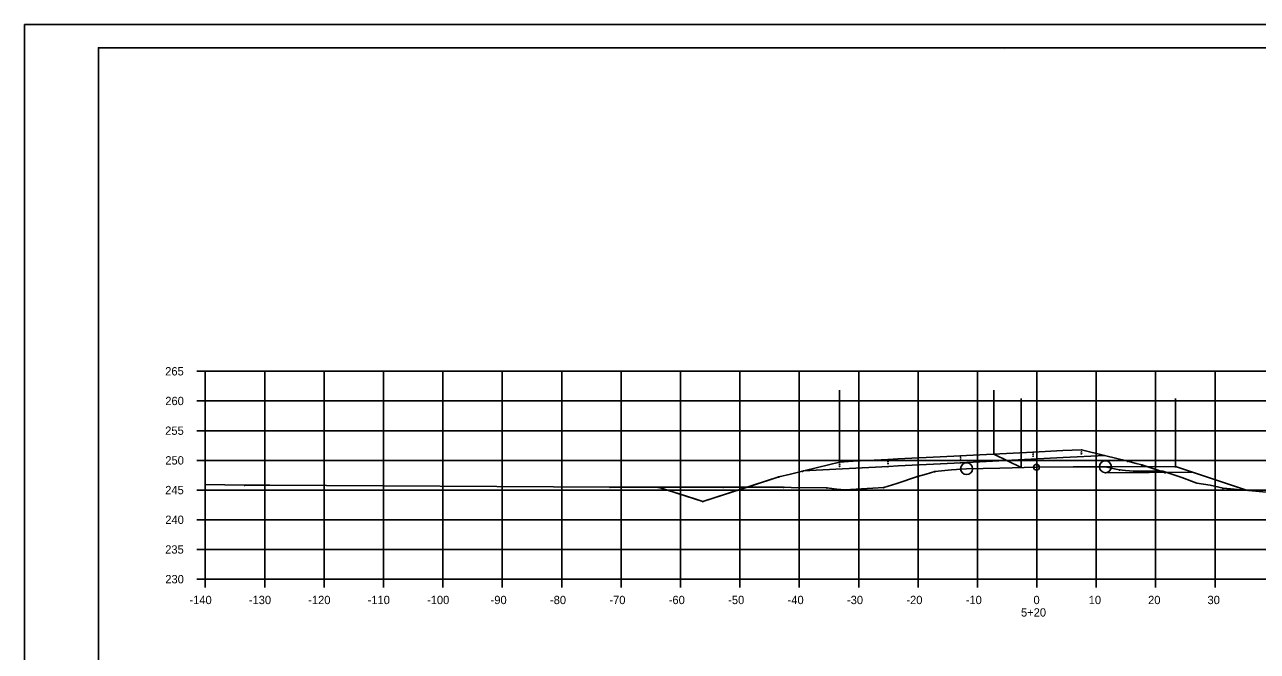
# Model space of a CAD drawing. Extents: x 1300404 to 1323571, y 234004 to 252077.
# Drawn here: x 1315546.9 to 1315754.4, y 241809.6 to 241915.1 of the extents above; entities that cross this region are included whole.
import ezdxf

# ---------------------------------------------------------------- set-up
doc = ezdxf.new("R2010")
doc.units = 0
for name, color, linetype in [('Default', 7, 'Continuous'), ('R_Axis', 7, 'Continuous'), ('R_Axis Annot', 7, 'Continuous'), ('R_Border', 7, 'Continuous'), ('R_Draft', 7, 'Continuous'), ('R_Exist Surface', 7, 'Continuous'), ('R_Fin Surface', 7, 'Continuous'), ('R_Grid', 7, 'Continuous'), ('R_MOT', 7, 'Continuous'), ('R_No Plot', 7, 'Continuous')]:
    doc.layers.add(name, color=color, linetype=linetype)

msp = doc.modelspace()

# ---------------------------------------------------------------- linework, layer by layer
at = {"layer": 'Default'}
for p, q in [((1315559.28, 241911.23), (1315875.46, 241911.23)), ((1315559.28, 241705.77), (1315559.28, 241911.23))]:
    msp.add_line(p, q, dxfattribs=at)
at = {"layer": 'R_Axis'}
for p, q in [((1315575.88, 241856.77), (1315577.28, 241856.77)), ((1315577.28, 241821.77), (1315577.28, 241856.77)), ((1315575.88, 241851.77), (1315577.28, 241851.77)), ((1315575.88, 241846.77), (1315577.28, 241846.77)), ((1315575.88, 241841.77), (1315577.28, 241841.77)), ((1315575.88, 241836.77), (1315577.28, 241836.77)), ((1315575.88, 241831.77), (1315577.28, 241831.77)), ((1315575.88, 241826.77), (1315577.28, 241826.77)), ((1315575.88, 241821.77), (1315577.28, 241821.77)), ((1315577.28, 241821.77), (1315857.28, 241821.77)), ((1315577.28, 241820.37), (1315577.28, 241821.77)), ((1315587.28, 241820.37), (1315587.28, 241821.77)), ((1315597.28, 241820.37), (1315597.28, 241821.77)), ((1315607.28, 241820.37), (1315607.28, 241821.77)), ((1315617.28, 241820.37), (1315617.28, 241821.77)), ((1315627.28, 241820.37), (1315627.28, 241821.77)), ((1315637.28, 241820.37), (1315637.28, 241821.77)), ((1315647.28, 241820.37), (1315647.28, 241821.77)), ((1315657.28, 241820.37), (1315657.28, 241821.77)), ((1315667.28, 241820.37), (1315667.28, 241821.77)), ((1315677.28, 241820.37), (1315677.28, 241821.77)), ((1315687.28, 241820.37), (1315687.28, 241821.77)), ((1315697.28, 241820.37), (1315697.28, 241821.77)), ((1315707.28, 241820.37), (1315707.28, 241821.77)), ((1315717.28, 241820.37), (1315717.28, 241821.77)), ((1315727.28, 241820.37), (1315727.28, 241821.77)), ((1315737.28, 241820.37), (1315737.28, 241821.77)), ((1315747.28, 241820.37), (1315747.28, 241821.77))]:
    msp.add_line(p, q, dxfattribs=at)
at = {"layer": 'R_Border'}
msp.add_line((1315711.8, 241910.97), (1315711.8, 241910.97), dxfattribs=at)
msp.add_line((1315711.8, 241910.97), (1315711.8, 241910.97), dxfattribs=at)
at = {"layer": 'R_Draft'}
for points in [[(1315724.78, 241843.62), (1315724.83, 241843.52), (1315724.73, 241843.52)], [(1315724.78, 241843.29), (1315724.83, 241843.19), (1315724.73, 241843.19)], [(1315684.06, 241841.53), (1315684.11, 241841.43), (1315684.01, 241841.43)], [(1315684.06, 241841.19), (1315684.11, 241841.09), (1315684.01, 241841.09)], [(1315692.22, 241841.96), (1315692.27, 241841.86), (1315692.17, 241841.86)], [(1315692.22, 241841.63), (1315692.27, 241841.53), (1315692.17, 241841.53)], [(1315692.22, 241841.3), (1315692.27, 241841.2), (1315692.17, 241841.2)], [(1315704.44, 241842.6), (1315704.49, 241842.5), (1315704.39, 241842.5)], [(1315704.44, 241842.27), (1315704.49, 241842.17), (1315704.39, 241842.17)], [(1315704.44, 241841.94), (1315704.49, 241841.84), (1315704.39, 241841.84)], [(1315704.44, 241841.43), (1315704.49, 241841.33), (1315704.39, 241841.33)], [(1315716.64, 241843.22), (1315716.69, 241843.12), (1315716.59, 241843.12)], [(1315716.64, 241842.89), (1315716.69, 241842.79), (1315716.59, 241842.79)], [(1315716.64, 241842.56), (1315716.69, 241842.46), (1315716.59, 241842.46)], [(1315716.64, 241842.05), (1315716.69, 241841.95), (1315716.59, 241841.95)], [(1315724.78, 241842.96), (1315724.83, 241842.86), (1315724.73, 241842.86)], [(1315732.58, 241841.66), (1315732.63, 241841.56), (1315732.53, 241841.56)], [(1315677.83, 241840.02), (1315677.88, 241839.92), (1315677.78, 241839.92)], [(1315684.06, 241840.86), (1315684.11, 241840.76), (1315684.01, 241840.76)], [(1315692.22, 241840.8), (1315692.27, 241840.7), (1315692.17, 241840.7)], [(1315697.19, 241839.1), (1315697.24, 241839), (1315697.14, 241839)], [(1315700.09, 241839.94), (1315700.14, 241839.84), (1315700.04, 241839.84)], [(1315731.19, 241840.21), (1315731.24, 241840.11), (1315731.14, 241840.11)], [(1315733.56, 241840), (1315733.61, 241839.9), (1315733.51, 241839.9)], [(1315734.94, 241841.06), (1315734.99, 241840.96), (1315734.89, 241840.96)], [(1315738.49, 241839.98), (1315738.54, 241839.88), (1315738.44, 241839.88)], [(1315738.85, 241839.76), (1315738.9, 241839.66), (1315738.8, 241839.66)], [(1315738.85, 241839.76), (1315738.9, 241839.66), (1315738.8, 241839.66)], [(1315583.88, 241837.66), (1315583.93, 241837.56), (1315583.83, 241837.56)], [(1315645.42, 241837.32), (1315645.47, 241837.22), (1315645.37, 241837.22)], [(1315653.54, 241837.33), (1315653.59, 241837.23), (1315653.49, 241837.23)], [(1315653.54, 241837.33), (1315653.59, 241837.23), (1315653.49, 241837.23)], [(1315664.46, 241837.33), (1315664.51, 241837.23), (1315664.41, 241837.23)], [(1315673.86, 241839.06), (1315673.91, 241838.96), (1315673.81, 241838.96)], [(1315674.62, 241837.29), (1315674.67, 241837.19), (1315674.57, 241837.19)], [(1315681.93, 241837.2), (1315681.98, 241837.1), (1315681.88, 241837.1)], [(1315691.51, 241837.25), (1315691.56, 241837.15), (1315691.46, 241837.15)], [(1315744.24, 241838.01), (1315744.29, 241837.91), (1315744.19, 241837.91)], [(1315748.62, 241837.13), (1315748.67, 241837.03), (1315748.57, 241837.03)], [(1315684.93, 241836.87), (1315684.98, 241836.77), (1315684.88, 241836.77)], [(1315661.04, 241834.91), (1315661.09, 241834.81), (1315660.99, 241834.81)]]:
    msp.add_lwpolyline(points, close=True, dxfattribs=at)
at = {"layer": 'R_Exist Surface'}
msp.add_lwpolyline([(1315577.28, 241837.7), (1315583.88, 241837.61), (1315585.09, 241837.61), (1315588.14, 241837.59), (1315645.42, 241837.27), (1315662.69, 241837.28), (1315664.46, 241837.28), (1315667.61, 241837.27), (1315674.62, 241837.24), (1315675.9, 241837.21), (1315681.93, 241837.15), (1315683.58, 241836.93), (1315684.93, 241836.82), (1315689.66, 241837.09), (1315691.51, 241837.2), (1315693.71, 241837.9), (1315697.19, 241839.05), (1315698.67, 241839.46), (1315700.09, 241839.89), (1315702.93, 241840.15), (1315705.44, 241840.37), (1315711.04, 241840.48), (1315717.22, 241840.61), (1315723.37, 241840.66), (1315728.82, 241840.69), (1315730.59, 241840.29), (1315731.19, 241840.16), (1315732.22, 241840.06), (1315733.56, 241839.95), (1315734.81, 241839.94), (1315738.49, 241839.93), (1315741.67, 241838.91), (1315744.24, 241837.96), (1315746.44, 241837.57), (1315748.62, 241837.08), (1315756.55, 241836.38)], dxfattribs=at)
at = {"layer": 'R_Fin Surface'}
msp.add_lwpolyline([(1315653.54, 241837.28), (1315659.71, 241835.29), (1315661.04, 241834.86), (1315669.22, 241837.51), (1315673.86, 241839.01), (1315675.78, 241839.47), (1315677.83, 241839.97), (1315680.35, 241840.58), (1315684.06, 241841.48), (1315686.35, 241841.61), (1315692.22, 241841.91), (1315693.86, 241842.01), (1315701, 241842.37), (1315704.44, 241842.55), (1315705.44, 241842.6), (1315716.64, 241843.17), (1315721.67, 241843.42), (1315724.78, 241843.57), (1315728.65, 241842.6), (1315732.58, 241841.61), (1315734.02, 241841.24), (1315734.94, 241841.01), (1315736.31, 241840.56), (1315738.85, 241839.71)], dxfattribs=at)
at = {"layer": 'R_Grid'}
for p, q in [((1315577.28, 241856.77), (1315857.28, 241856.77)), ((1315577.28, 241821.77), (1315577.28, 241856.77)), ((1315587.28, 241821.77), (1315587.28, 241856.77)), ((1315597.28, 241821.77), (1315597.28, 241856.77)), ((1315607.28, 241821.77), (1315607.28, 241856.77)), ((1315617.28, 241821.77), (1315617.28, 241856.77)), ((1315627.28, 241821.77), (1315627.28, 241856.77)), ((1315637.28, 241821.77), (1315637.28, 241856.77)), ((1315647.28, 241821.77), (1315647.28, 241856.77)), ((1315657.28, 241821.77), (1315657.28, 241856.77)), ((1315667.28, 241821.77), (1315667.28, 241856.77)), ((1315677.28, 241821.77), (1315677.28, 241856.77)), ((1315687.28, 241821.77), (1315687.28, 241856.77)), ((1315697.28, 241821.77), (1315697.28, 241856.77)), ((1315707.28, 241821.77), (1315707.28, 241856.77)), ((1315717.28, 241821.77), (1315717.28, 241856.77)), ((1315727.28, 241821.77), (1315727.28, 241856.77)), ((1315737.28, 241821.77), (1315737.28, 241856.77)), ((1315747.28, 241821.77), (1315747.28, 241856.77)), ((1315577.28, 241851.77), (1315857.28, 241851.77)), ((1315577.28, 241846.77), (1315857.28, 241846.77)), ((1315577.28, 241841.77), (1315857.28, 241841.77)), ((1315577.28, 241836.77), (1315857.28, 241836.77)), ((1315577.28, 241831.77), (1315857.28, 241831.77)), ((1315577.28, 241826.77), (1315857.28, 241826.77)), ((1315577.28, 241821.77), (1315857.28, 241821.77))]:
    msp.add_line(p, q, dxfattribs=at)
at = {"layer": 'R_MOT'}
for p, q in [((1315684.06, 241841.48), (1315684.06, 241853.57)), ((1315710.06, 241842.83), (1315710.06, 241853.57)), ((1315714.61, 241840.56), (1315714.61, 241852.21)), ((1315740.61, 241840.56), (1315740.61, 241852.21)), ((1315710.06, 241842.83), (1315714.61, 241840.56)), ((1315728.82, 241840.69), (1315740.61, 241840.76)), ((1315728.82, 241839.69), (1315743.56, 241839.78)), ((1315740.61, 241840.76), (1315752.74, 241836.71))]:
    msp.add_line(p, q, dxfattribs=at)
msp.add_lwpolyline([(1315677.94, 241840), (1315692.28, 241840.75), (1315693.92, 241840.84), (1315701.06, 241841.2), (1315704.5, 241841.38), (1315705.5, 241841.43), (1315721.73, 241842.26), (1315728.71, 241842.58)], dxfattribs=at)
at = {"layer": 'R_No Plot'}
msp.add_line((1315546.87, 241915.12), (1315880.21, 241915.12), dxfattribs=at)
for points in [[(1315546.87, 241915.12), (1315880.21, 241915.12), (1315880.21, 241701.78), (1315546.87, 241701.78)], [(1315793.2, 241911.23), (1315793.2, 241901.35), (1315828.93, 241901.35), (1315828.93, 241898.43), (1315852.13, 241898.43), (1315852.13, 241876.31), (1315875.46, 241876.31), (1315875.46, 241705.77), (1315559.28, 241705.77), (1315559.28, 241911.23)]]:
    msp.add_lwpolyline(points, close=True, dxfattribs=at)
for points in [[(1315673.86, 241839.01), (1315661.04, 241834.86), (1315653.54, 241837.28)], [(1315673.86, 241839.01), (1315661.04, 241834.86), (1315653.54, 241837.28)], [(1315673.86, 241839.01), (1315661.04, 241834.86), (1315653.54, 241837.28)], [(1315673.86, 241839.01), (1315661.04, 241834.86), (1315653.54, 241837.28)], [(1315673.86, 241839.01), (1315661.04, 241834.86), (1315653.54, 241837.28)], [(1315661.04, 241834.86), (1315653.54, 241837.28)]]:
    msp.add_lwpolyline(points, dxfattribs=at)
for centre, radius in [((1315705.44, 241840.37), 1), ((1315728.82, 241840.69), 1), ((1315717.22, 241840.61), 0.5)]:
    msp.add_circle(centre, radius, dxfattribs=at)

# ---------------------------------------------------------------- texts
at = {"layer": 'R_Axis'}
msp.add_text('-', height=0.0001, dxfattribs=at).set_placement((1315577.28, 241821.77))
at = {"layer": 'R_Axis Annot'}
for s, p in [('265', (1315570.53, 241856.07)), ('260', (1315570.55, 241851.07)), ('255', (1315570.53, 241846.07)), ('250', (1315570.55, 241841.07)), ('245', (1315570.53, 241836.07)), ('240', (1315570.55, 241831.07)), ('235', (1315570.53, 241826.07)), ('230', (1315570.55, 241821.07)), ('-140', (1315574.61, 241817.57)), ('-130', (1315584.61, 241817.57)), ('-120', (1315594.61, 241817.57)), ('-110', (1315604.61, 241817.57)), ('-100', (1315614.61, 241817.57)), ('-90', (1315625.31, 241817.57)), ('-80', (1315635.31, 241817.57)), ('-70', (1315645.31, 241817.57)), ('-60', (1315655.31, 241817.57)), ('-50', (1315665.31, 241817.57)), ('-40', (1315675.31, 241817.57)), ('-30', (1315685.31, 241817.57)), ('-20', (1315695.31, 241817.57)), ('-10', (1315705.31, 241817.57)), ('0', (1315716.71, 241817.57)), ('10', (1315726.01, 241817.57)), ('20', (1315736.01, 241817.57)), ('30', (1315746.01, 241817.57)), ('5+20', (1315714.61, 241815.47))]:
    msp.add_text(s, height=1.4, dxfattribs=at).set_placement(p)

doc.saveas('drawing.dxf')
